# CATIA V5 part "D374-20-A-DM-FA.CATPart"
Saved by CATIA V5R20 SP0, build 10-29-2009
Part number: D374-20-A-DM-FA
Bounding box of the stored display mesh (mm): x -16 to 0.35, y -10 to 10, z -10 to 10
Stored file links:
  C:\Users\Utente\Desktop\IO LAVORO\3D X SITO CF\X SITO\PLASTICA\D374\D374-20-A-DM-FA.CATPart
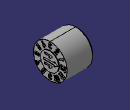
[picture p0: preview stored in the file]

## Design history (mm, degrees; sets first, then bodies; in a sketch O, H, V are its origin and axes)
Set1
  DatumSurface1 to DatumSurface222 "D374-20-A-DM-FA"
Body1 (main body)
